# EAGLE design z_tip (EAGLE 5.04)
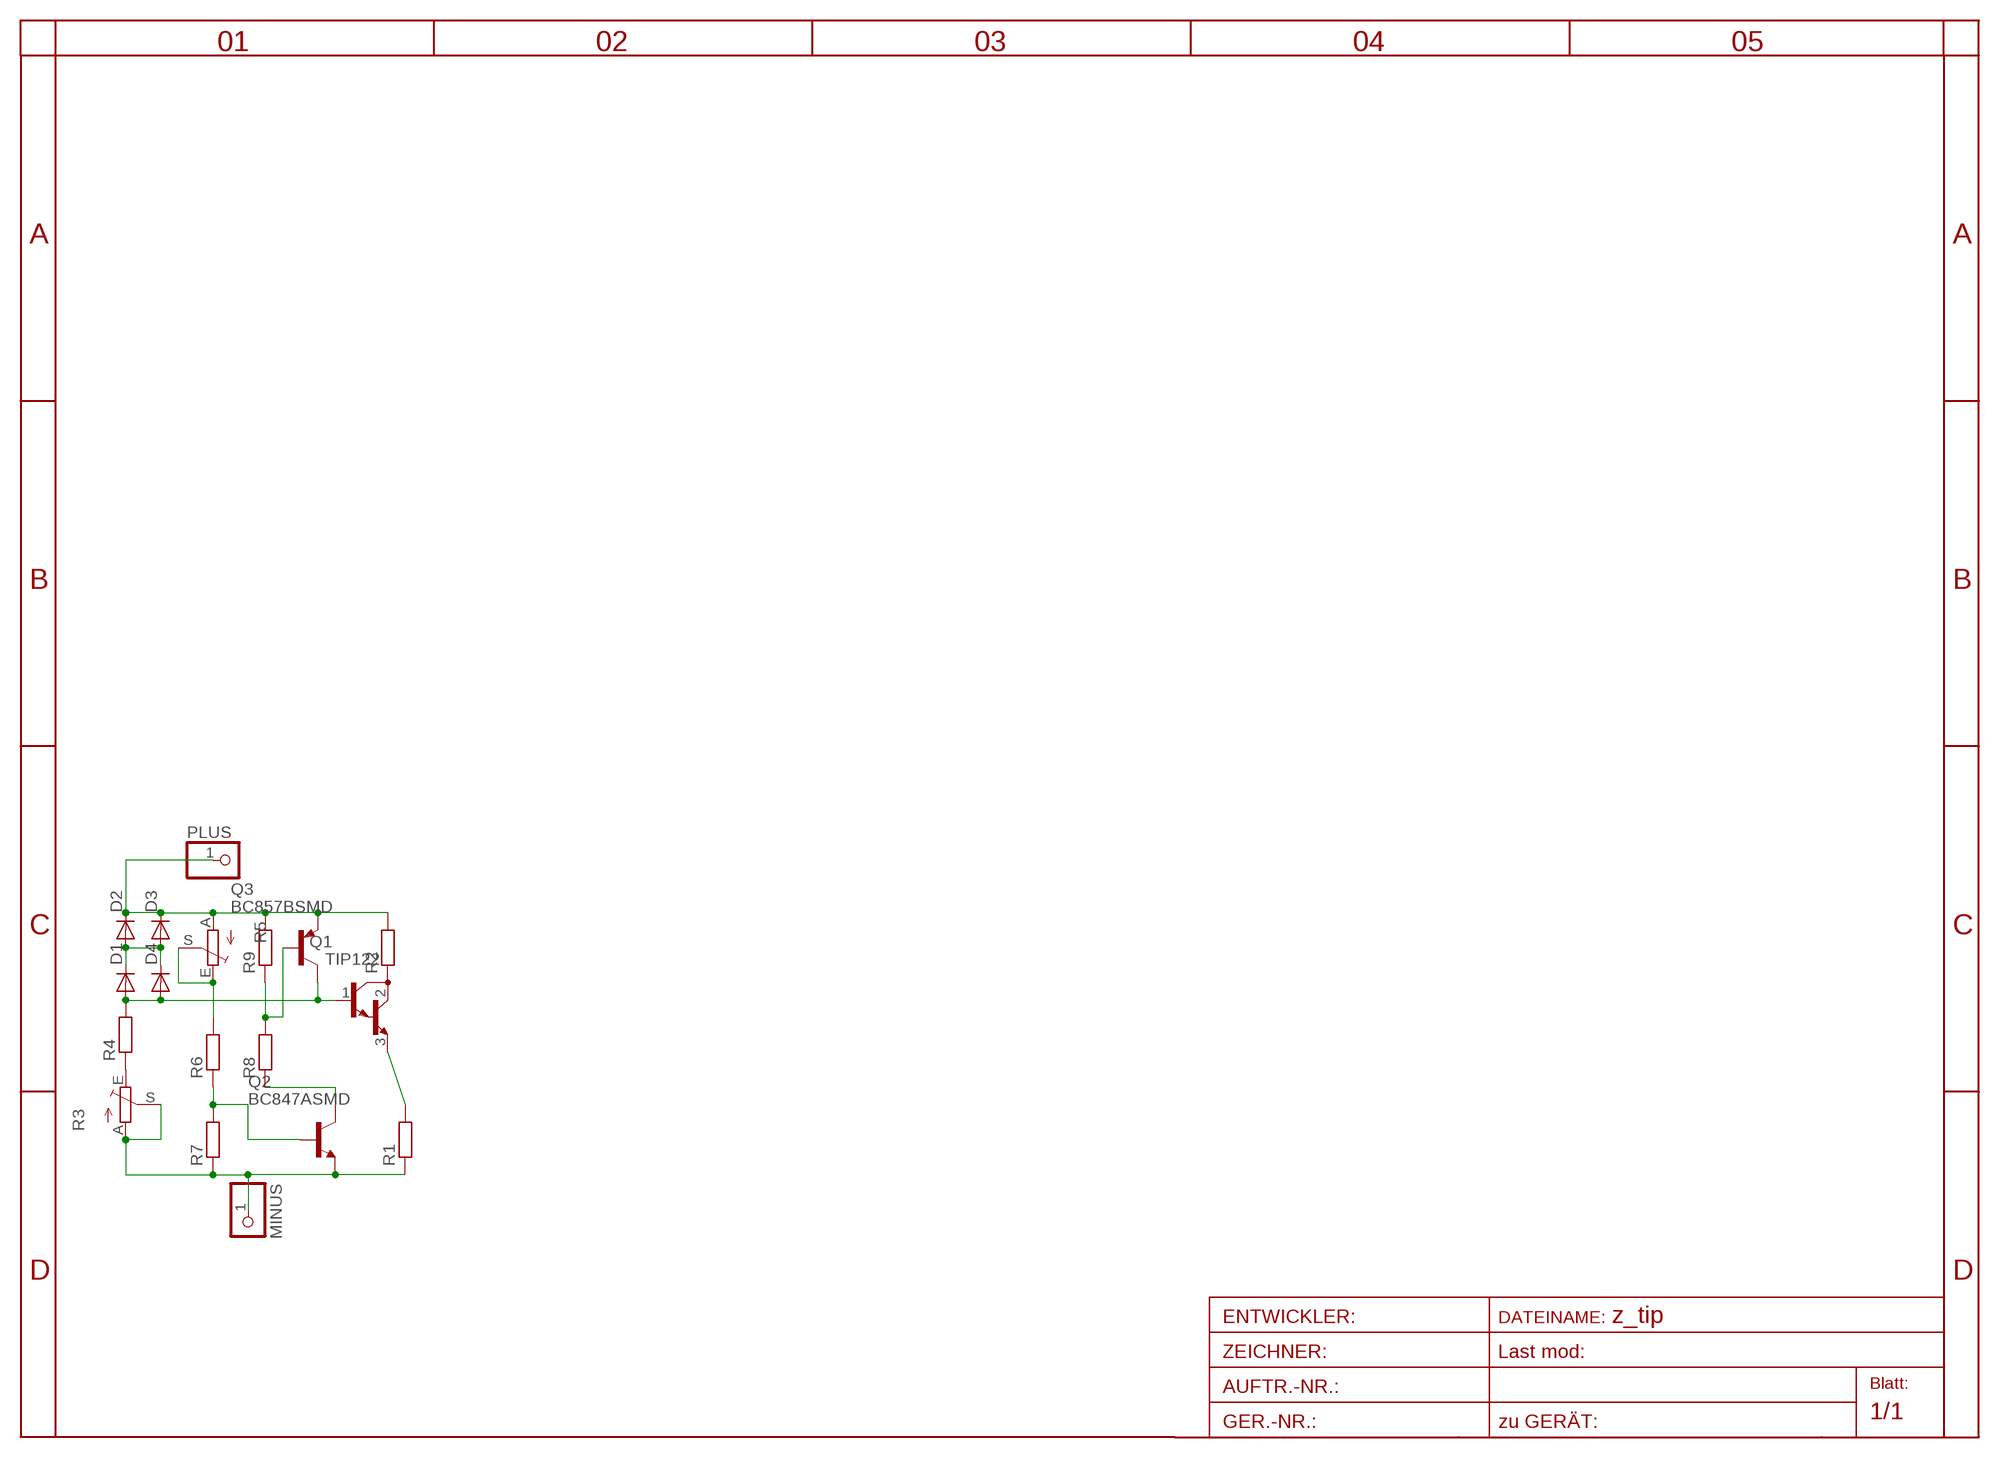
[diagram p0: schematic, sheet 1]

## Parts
D1  DIODE-MINIMELF  [MINIMELF]
D2  DIODE-MINIMELF  [MINIMELF]
D3  DIODE-D-2.5  [D-2.5]
D4  DIODE-D-2.5  [D-2.5]
MINUS  PINHD-1X1  [1X01]
PLUS  PINHD-1X1  [1X01]
Q1  TIP122  [TO220]
Q2  BC847ASMD  [SOT23]
Q3  BC857BSMD  [SOT23-BEC]
R1  R-EU_0411/15  [0411/15]
R2  R-EU_0922V  [0922V]
R3  TRIM_EU-CA6V  [CA6V]
R4  R-EU_R1206  [R1206]
R5  TRIM_EU-CA6V  [CA6V]
R6  R-EU_R1206  [R1206]
R7  R-EU_R1206  [R1206]
R8  R-EU_R1206  [R1206]
R9  R-EU_R1206  [R1206]

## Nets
C: Q1.2(C) R2.1
E: Q1.3(E) R1.2
MINUS: MINUS.1 Q2.2(E) R1.1 R3.A R3.S R7.1
N$1: D1.A D4.A Q1.1(B) Q3.C R4.2
N$2: D1.C D2.A D3.A D4.C
N$3: R3.E R4.1
N$4: Q3.B R8.2 R9.1
N$6: Q2.3(C) R8.1
N$7: R5.E R5.S R6.2
N$8: Q2.1(B) R6.1 R7.2
PLUS: D2.C D3.C PLUS.1 Q3.E R2.2 R5.A R9.2

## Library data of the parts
D1-D4 = diode-1:DIODE-: DIODE
MINUS PLUS = pinhead:PINHD-1X1: PIN HEADER
Q1 = transistor-npn:TIP122*: NPN Darlington Transistor
Q2 = transistor-npn:BC847*: NPN Transistor
Q3 = transistor-pnp:BC857*: PNP Transistror
R1 R2 R4 R6-R9 = rcl:R-EU_: RESISTOR, European symbol
R3 R5 = pot:TRIM_EU-: POTENTIOMETER

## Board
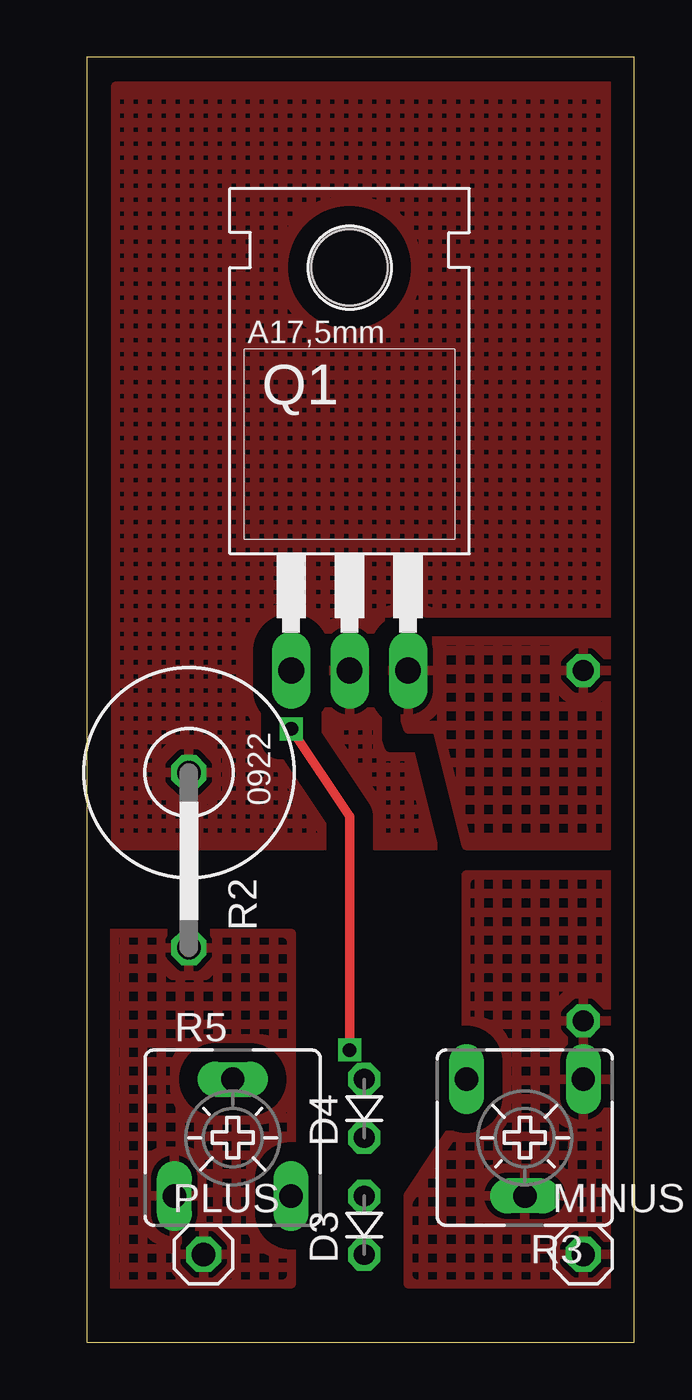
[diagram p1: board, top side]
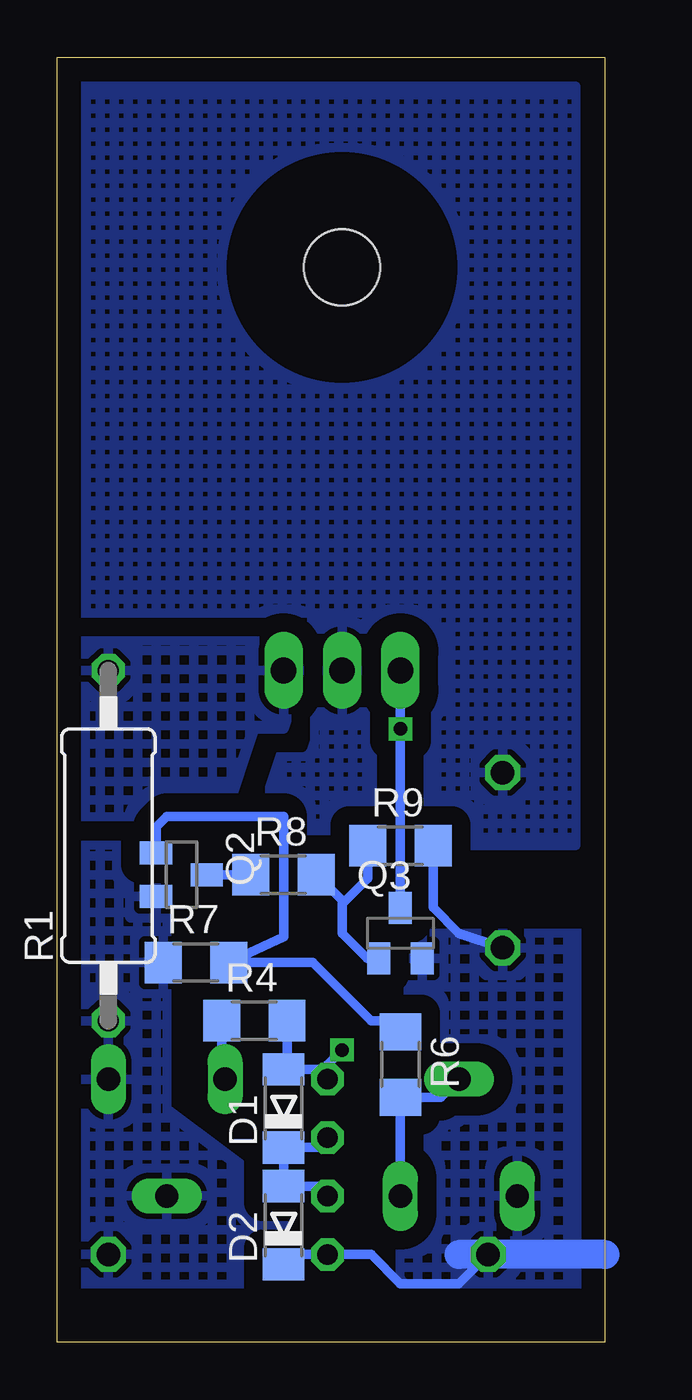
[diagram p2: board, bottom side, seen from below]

Size 23.8 x 55.87 mm. Coordinates in mm from the lower left corner, seen from the top.
Outline: 0,0 23.8,0 23.8,55.87 0,55.87 0,0
Copper layers (1*16): Top 0.035mm / dielectric 1.5mm / Bottom 0.035mm
Design rules "default": minimum track width 10mil, minimum drill 24mil, track to track 8mil, track to pad 8mil, pad to pad 8mil, via to via 8mil, smd to smd 8mil, copper to edge 40mil, drill to drill 8mil, minimum pad ring 10mil, minimum via ring 8mil, stop-mask expansion 4mil, vias tented up to drill 0mil, thermal gap 10mil

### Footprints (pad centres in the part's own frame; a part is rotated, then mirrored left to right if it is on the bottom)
MINIMELF = smd 1.4 x 1.8: A 1.7,0; C -1.7,0
D-2.5 = drill 0.9 octagon: A 1.27,0; C -1.27,0
1X01 = drill 1.016 octagon: 1 0,0
TO220 = drill 1.118 long: 1 -2.54,-6.35; 2 0,-6.35; 3 2.54,-6.35 | hole 3.302: 0,11.176
SOT23 = smd 1 x 1.4: 1 -0.95,-1.1; 2 0.95,-1.1; 3 0,1.1
SOT23-BEC = smd 1 x 1.4: B -0.95,-1.1; C 0,1.1; E 0.95,-1.1
0411/15 = drill 0.914 octagon: 1 -7.62,0; 2 7.62,0
0922V = drill 1.016 octagon: 1 -5.08,0; 2 2.54,0
CA6V = drill 1.016 long: A -2.54,-2.54; E 2.54,-2.54; S 0,2.54
R1206 = smd 1.6 x 1.803: 1 -1.422,0; 2 1.422,0

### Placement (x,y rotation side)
D1  13.97,10.16 90 bottom
D2  13.97,5.08 90 bottom
D3  12.06,5.08 90 top
D4  12.06,10.16 90 top
MINUS  21.59,3.81 0 top
PLUS  5.08,3.81 0 top
Q1  11.43,35.56 0 top
Q2  18.41,20.32 270 bottom
Q3  8.89,17.78 0 bottom
R1  21.59,21.59 90 bottom
R2  4.45,19.68 270 top
R3  19.05,8.89 180 top
R4  15.24,13.97 0 bottom
R5  6.35,8.89 0 top
R6  8.89,12.06 270 bottom
R7  17.78,16.51 0 bottom
R8  13.97,20.32 0 bottom
R9  8.89,21.59 0 bottom

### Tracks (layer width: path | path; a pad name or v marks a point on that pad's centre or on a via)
C
  pour Bottom (isolate 0.813, rank 3, hatched): 22.86,21.59 1.27,21.59 1.27,54.61 22.86,54.61
  pour Top (isolate 0.813, rank 3, hatched): 22.86,21.59 1.27,21.59 1.27,54.61 22.86,54.61
E
  pour Bottom (isolate 0.813, rank 2, hatched): 12.7,30.48 22.86,30.48 22.86,22.86 16.51,22.86 15.24,26.67 13.97,26.67
  pour Top (isolate 0.813, rank 2, hatched): 12.7,30.48 22.86,30.48 22.86,21.59 16.51,21.59 15.24,26.67 13.97,26.67
MINUS
  pour Bottom (isolate 0.813, hatched): 19.05,21.59 22.86,21.59 22.86,2.54 13.97,2.54 13.97,6.35 19.05,10.16
  pour Top (isolate 0.813, hatched): 16.51,20.32 22.86,20.32 22.86,2.54 13.97,2.54 13.97,6.35 16.51,10.16
N$1  (via drill 0.6)
  Top 0.406: v11.43,12.7 11.43,22.86 v8.89,26.67
  Bottom 0.406: 13.82,11.86 D1.A | 13.82,11.86 R4.2 | v11.43,12.7 12.06,12.06 D4.A 12.49,11.86 13.82,11.86 | Q1.1 v8.89,26.67 Q3.C
N$2
  Bottom 0.406: D4.C 12.49,8.46 D1.C D2.A 12.49,6.78 D3.A
N$3
  Bottom 0.406: R4.1 16.66,11.58 R3.E
N$4
  Bottom 0.406: Q3.B 10.33,16.68 11.43,17.78 11.43,19.05 | 11.43,19.05 11.43,19.2 R8.2 | R9.1 10.31,20.17 11.43,19.05
N$6
  Bottom 0.406: R8.1 Q2.3
N$7
  Bottom 0.406: R5.S 7.14,10.64 R6.2 R5.E
N$8
  Bottom 0.406: Q2.1 19.52,22.39 19.05,22.86 13.97,22.86 13.97,17.63 R7.2 12.7,16.51 10.16,13.97 9.04,13.97 R6.1
PLUS
  Bottom 0.406: R9.2 7.47,18.9 6.35,17.78 R2.2 | PLUS.1 6.35,2.54 8.89,2.54 10.16,3.81 D3.C 13.54,3.81 D2.C
  Bottom 1.27: 0,3.81 PLUS.1 6.35,3.81
  pour Bottom (isolate 0.813, hatched): 0,17.78 8.89,17.78 8.89,2.54 0,2.54
  pour Top (isolate 0.813, hatched): 0,17.78 8.89,17.78 8.89,2.54 0,2.54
